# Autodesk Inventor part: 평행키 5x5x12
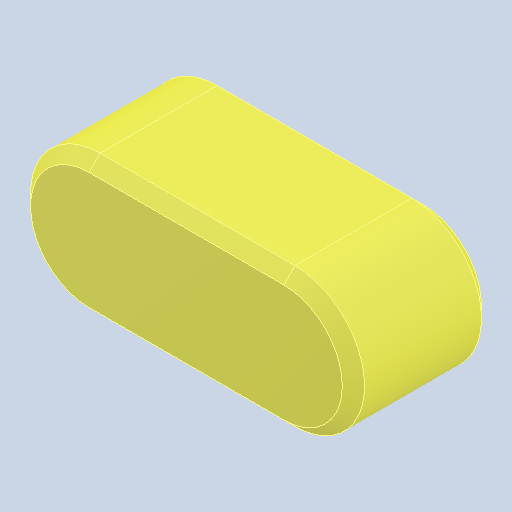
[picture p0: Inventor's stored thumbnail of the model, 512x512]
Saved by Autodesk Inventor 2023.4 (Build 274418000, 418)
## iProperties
Created: 2024-04
Part Number: 평행키 5x5x12
Material: 강철, 연강
Description: 키 및 해당 키홈
Document SubType Name: Modeling
Designer: EDU
Density: 7.85 g/cm^3
Appearance: 기본값
Author: jhkim
Sending System: Autodesk Inventor 2025
Preprocessor: ST-DEVELOPER v20
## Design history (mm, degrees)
node "평행키 5x5x121"
node "솔리드1"
body "Solid1"
